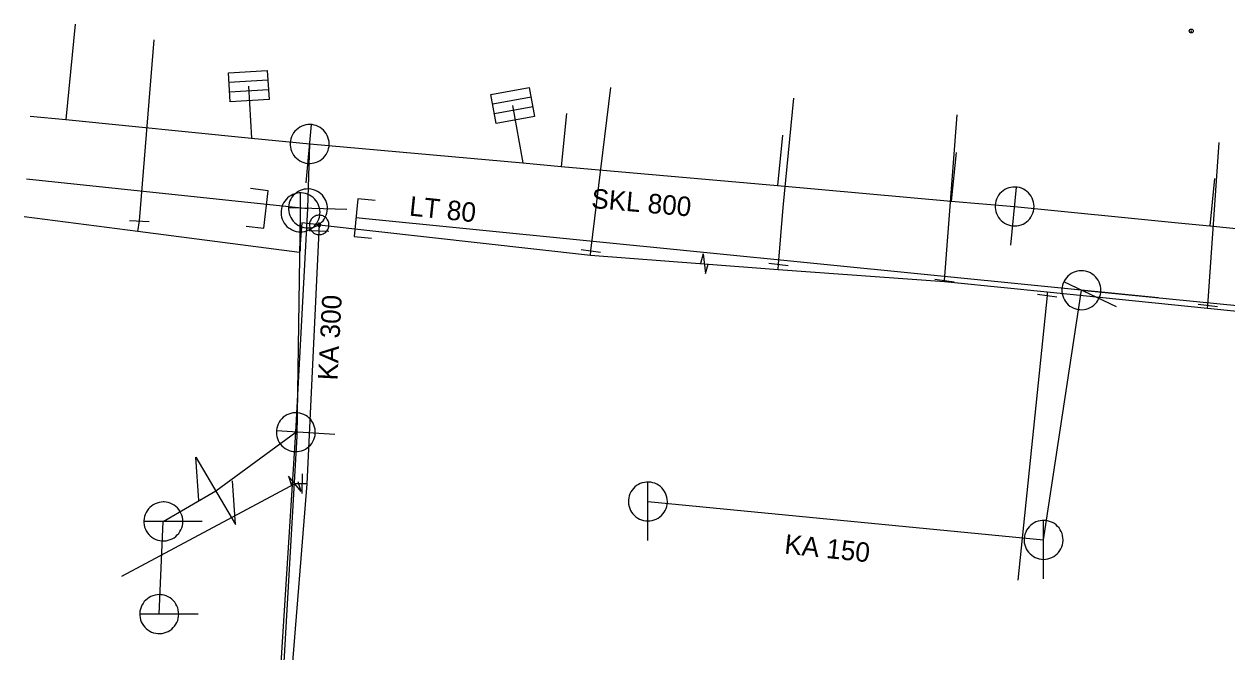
# Model space of a CAD drawing. Extents: x -783064 to -782702, y -1007904 to -1007145.
# Drawn here: x -783034.1 to -782972.3, y -1007414.2 to -1007381.9 of the extents above; entities that cross this region are included whole.
import ezdxf

# ---------------------------------------------------------------- set-up
doc = ezdxf.new("R2010")
doc.units = 0
doc.header["$LTSCALE"] = 0.4
doc.header["$PDMODE"] = 32
doc.header["$PDSIZE"] = 0.2
for name, color, linetype, lineweight in [('1', 7, 'Continuous', 13), ('11', 7, 'Continuous', 13), ('13', 7, 'Continuous', 13), ('14', 7, 'Continuous', 13), ('17', 7, 'Continuous', 25), ('22', 7, 'Continuous', 13), ('31', 7, 'Continuous', 13), ('34', 7, 'Continuous', 13), ('47', 7, 'Continuous', 13)]:
    doc.layers.add(name, color=color, linetype=linetype, lineweight=lineweight)

msp = doc.modelspace()

# ---------------------------------------------------------------- linework, layer by layer
at = {"layer": '1'}
msp.add_point((-782974.16, -1007382.289), dxfattribs=at)
at = {"layer": '11'}
for p, q in [((-783031.44, -1007381.93), (-783031.93, -1007386.84)), ((-783022.549, -1007385.119), (-783022.39, -1007387.79)), ((-783009, -1007386.109), (-783008.46, -1007389.06)), ((-783006.23, -1007386.52), (-783006.5, -1007389.24)), ((-782995.14, -1007387.63), (-782995.399, -1007390.22)), ((-782986.23, -1007388.53), (-782986.48, -1007391.02)), ((-782972.969, -1007389.86), (-782973.21, -1007392.3)), ((-783024.234, -1007405.901), (-783020.12, -1007402.89)), ((-783026.922, -1007407.474), (-783024.234, -1007405.901)), ((-783027.131, -1007412.234), (-783026.922, -1007407.474))]:
    msp.add_line(p, q, dxfattribs=at)
at = {"layer": '13'}
for p, q in [((-783028.152, -1007392.037), (-783027.383, -1007382.737)), ((-783004.98, -1007393.575), (-783003.958, -1007385.184)), ((-782986.819, -1007395.099), (-782986.17, -1007386.59)), ((-782973.317, -1007396.376), (-782972.732, -1007388.015)), ((-782981.562, -1007395.872), (-782983.061, -1007410.494)), ((-783020.171, -1007405.541), (-783029.074, -1007410.307)), ((-783019.784, -1007405.535), (-783020.171, -1007405.541))]:
    msp.add_line(p, q, dxfattribs=at)
msp.add_lwpolyline([(-782995.339, -1007394.269), (-782995.109, -1007391.35), (-782994.559, -1007385.73)], dxfattribs=at)
at = {"layer": '14', "lineweight": 25}
for p, q in [((-783019.5, -1007391.399), (-783019.409, -1007388.089)), ((-783033.95, -1007389.875), (-783019.5, -1007391.399)), ((-783020.12, -1007402.89), (-783019.5, -1007391.399)), ((-783017.033, -1007391.872), (-782975.859, -1007395.965)), ((-782981.739, -1007408.42), (-782979.802, -1007395.6)), ((-783023.759, -1007460.525), (-783020.12, -1007402.89)), ((-783002.05, -1007406.45), (-782981.739, -1007408.42))]:
    msp.add_line(p, q, dxfattribs=at)
at = {"layer": '14'}
for p, q in [((-783028.23, -1007392.582), (-783028.152, -1007392.037)), ((-783018.921, -1007392.244), (-783018.931, -1007392.572)), ((-783004.991, -1007393.792), (-783004.98, -1007393.575)), ((-782995.359, -1007394.53), (-782995.339, -1007394.269)), ((-782986.82, -1007395.16), (-782986.819, -1007395.099)), ((-782981.552, -1007395.683), (-782981.562, -1007395.872)), ((-782973.329, -1007396.518), (-782973.317, -1007396.376)), ((-783019.55, -1007405.538), (-783019.784, -1007405.535))]:
    msp.add_line(p, q, dxfattribs=at)
at = {"layer": '14', "lineweight": 25}
for points in [[(-783033.754, -1007386.657), (-783031.93, -1007386.84), (-783022.39, -1007387.79), (-783019.409, -1007388.089)], [(-783019.409, -1007388.089), (-783008.46, -1007389.06), (-783006.5, -1007389.24), (-782995.399, -1007390.22), (-782986.48, -1007391.02), (-782983.228, -1007391.299)], [(-782983.228, -1007391.299), (-782974.833, -1007392.137), (-782973.21, -1007392.3), (-782963.44, -1007393.28), (-782954.43, -1007394.18), (-782945.989, -1007395.03), (-782935.15, -1007396.194), (-782929.789, -1007396.77)], [(-783023.489, -1007462.841), (-783020.044, -1007403.091), (-783019.879, -1007391.6)], [(-782979.802, -1007395.6), (-782957.907, -1007397.75), (-782930.949, -1007400.43)]]:
    msp.add_lwpolyline(points, dxfattribs=at)
at = {"layer": '17'}
for points in [[(-783018.921, -1007392.244), (-783019.804, -1007392.144), (-783019.93, -1007393.66), (-783028.23, -1007392.582), (-783034.069, -1007391.825)], [(-783018.931, -1007392.572), (-783019.55, -1007405.538), (-783022.008, -1007435.982), (-783023.248, -1007462.969), (-783023.271, -1007463.144), (-783023.528, -1007465.299), (-783024.585, -1007485.409)], [(-783018.921, -1007392.244), (-783004.991, -1007393.792), (-782999.155, -1007394.238)], [(-782999.155, -1007394.238), (-782995.359, -1007394.53), (-782986.82, -1007395.16), (-782986.309, -1007395.2), (-782981.552, -1007395.683), (-782973.329, -1007396.518), (-782967.743, -1007397.085), (-782962.101, -1007397.658), (-782955.68, -1007398.31), (-782946.21, -1007399.37), (-782941.319, -1007399.909)]]:
    msp.add_lwpolyline(points, dxfattribs=at)
at = {"layer": '22'}
for p, q in [((-783021.554, -1007384.815), (-783023.55, -1007384.935)), ((-783021.524, -1007385.314), (-783023.52, -1007385.434)), ((-783008.049, -1007385.687), (-783010.016, -1007386.047)), ((-783007.959, -1007386.179), (-783009.926, -1007386.539)), ((-783019.585, -1007390.081), (-783019.32, -1007387.093)), ((-783019.879, -1007393.6), (-783019.878, -1007390.6)), ((-782983.426, -1007393.289), (-782983.128, -1007390.304)), ((-783017.5, -1007391.453), (-783020.499, -1007391.371)), ((-782977.992, -1007396.454), (-782980.705, -1007395.173)), ((-783018.123, -1007403.016), (-783021.117, -1007402.827)), ((-783002.05, -1007408.45), (-783002.049, -1007405.45)), ((-783024.921, -1007407.474), (-783027.921, -1007407.473)), ((-782981.739, -1007410.42), (-782981.738, -1007407.42)), ((-783025.13, -1007412.234), (-783028.13, -1007412.233))]:
    msp.add_line(p, q, dxfattribs=at)
for points in [[(-783021.494, -1007385.813), (-783023.49, -1007385.933), (-783023.58, -1007384.435), (-783021.584, -1007384.316)], [(-783007.869, -1007386.671), (-783009.836, -1007387.031), (-783010.106, -1007385.555), (-783008.139, -1007385.195)], [(-783018.412, -1007388.177), (-783018.409, -1007388.068), (-783018.417, -1007387.959), (-783018.438, -1007387.851), (-783018.469, -1007387.747), (-783018.512, -1007387.646), (-783018.566, -1007387.55), (-783018.63, -1007387.461), (-783018.703, -1007387.381), (-783018.785, -1007387.307), (-783018.874, -1007387.244), (-783018.969, -1007387.19), (-783019.071, -1007387.148), (-783019.176, -1007387.117), (-783019.283, -1007387.097), (-783019.393, -1007387.089), (-783019.502, -1007387.094), (-783019.611, -1007387.109), (-783019.717, -1007387.137), (-783019.819, -1007387.177), (-783019.915, -1007387.227), (-783020.007, -1007387.288), (-783020.091, -1007387.358), (-783020.167, -1007387.437), (-783020.234, -1007387.524), (-783020.29, -1007387.617), (-783020.336, -1007387.716), (-783020.372, -1007387.821), (-783020.395, -1007387.927), (-783020.407, -1007388.037), (-783020.406, -1007388.146), (-783020.395, -1007388.254), (-783020.37, -1007388.361), (-783020.335, -1007388.464), (-783020.289, -1007388.564), (-783020.231, -1007388.657), (-783020.164, -1007388.744), (-783020.088, -1007388.823), (-783020.004, -1007388.892), (-783019.913, -1007388.953), (-783019.815, -1007389.003), (-783019.713, -1007389.042), (-783019.607, -1007389.069), (-783019.498, -1007389.085), (-783019.389, -1007389.089), (-783019.28, -1007389.08), (-783019.173, -1007389.061), (-783019.067, -1007389.029), (-783018.966, -1007388.986), (-783018.871, -1007388.932), (-783018.782, -1007388.868), (-783018.7, -1007388.795), (-783018.628, -1007388.714), (-783018.564, -1007388.625), (-783018.511, -1007388.529), (-783018.468, -1007388.429), (-783018.436, -1007388.323), (-783018.417, -1007388.215)], [(-783018.879, -1007391.6), (-783018.884, -1007391.491), (-783018.902, -1007391.383), (-783018.932, -1007391.277), (-783018.972, -1007391.176), (-783019.024, -1007391.079), (-783019.086, -1007390.989), (-783019.158, -1007390.906), (-783019.238, -1007390.832), (-783019.326, -1007390.766), (-783019.42, -1007390.711), (-783019.52, -1007390.666), (-783019.625, -1007390.633), (-783019.732, -1007390.611), (-783019.841, -1007390.601), (-783019.951, -1007390.603), (-783020.059, -1007390.617), (-783020.166, -1007390.642), (-783020.269, -1007390.679), (-783020.367, -1007390.728), (-783020.459, -1007390.786), (-783020.545, -1007390.855), (-783020.622, -1007390.932), (-783020.691, -1007391.018), (-783020.75, -1007391.11), (-783020.798, -1007391.208), (-783020.835, -1007391.311), (-783020.861, -1007391.418), (-783020.875, -1007391.526), (-783020.878, -1007391.636), (-783020.868, -1007391.745), (-783020.847, -1007391.852), (-783020.813, -1007391.956), (-783020.769, -1007392.056), (-783020.714, -1007392.151), (-783020.648, -1007392.239), (-783020.574, -1007392.319), (-783020.491, -1007392.391), (-783020.401, -1007392.453), (-783020.305, -1007392.505), (-783020.203, -1007392.546), (-783020.098, -1007392.576), (-783019.99, -1007392.594), (-783019.88, -1007392.6), (-783019.771, -1007392.594), (-783019.663, -1007392.576), (-783019.558, -1007392.547), (-783019.456, -1007392.506), (-783019.359, -1007392.454), (-783019.269, -1007392.392), (-783019.186, -1007392.321), (-783019.111, -1007392.241), (-783019.046, -1007392.153), (-783018.99, -1007392.059), (-783018.946, -1007391.959), (-783018.912, -1007391.855), (-783018.89, -1007391.747), (-783018.88, -1007391.638)], [(-783019.472, -1007390.399), (-783019.581, -1007390.402), (-783019.689, -1007390.417), (-783019.796, -1007390.444), (-783019.898, -1007390.481), (-783019.997, -1007390.531), (-783020.088, -1007390.59), (-783020.173, -1007390.66), (-783020.249, -1007390.738), (-783020.318, -1007390.824), (-783020.375, -1007390.916), (-783020.423, -1007391.015), (-783020.459, -1007391.119), (-783020.484, -1007391.226), (-783020.497, -1007391.334), (-783020.498, -1007391.444), (-783020.487, -1007391.553), (-783020.464, -1007391.66), (-783020.43, -1007391.764), (-783020.384, -1007391.864), (-783020.329, -1007391.957), (-783020.262, -1007392.045), (-783020.187, -1007392.124), (-783020.103, -1007392.195), (-783020.013, -1007392.257), (-783019.916, -1007392.308), (-783019.814, -1007392.347), (-783019.708, -1007392.376), (-783019.6, -1007392.393), (-783019.49, -1007392.398), (-783019.381, -1007392.391), (-783019.273, -1007392.373), (-783019.169, -1007392.342), (-783019.067, -1007392.301), (-783018.971, -1007392.248), (-783018.881, -1007392.185), (-783018.799, -1007392.113), (-783018.725, -1007392.032), (-783018.661, -1007391.944), (-783018.606, -1007391.849), (-783018.562, -1007391.748), (-783018.529, -1007391.644), (-783018.508, -1007391.537), (-783018.499, -1007391.427), (-783018.502, -1007391.318), (-783018.517, -1007391.209), (-783018.544, -1007391.103), (-783018.582, -1007391), (-783018.631, -1007390.902), (-783018.691, -1007390.81), (-783018.759, -1007390.725), (-783018.837, -1007390.648), (-783018.924, -1007390.581), (-783019.016, -1007390.522), (-783019.115, -1007390.476), (-783019.218, -1007390.439), (-783019.325, -1007390.414), (-783019.434, -1007390.401)], [(-782982.232, -1007391.398), (-782982.228, -1007391.289), (-782982.235, -1007391.18), (-782982.254, -1007391.072), (-782982.284, -1007390.967), (-782982.326, -1007390.865), (-782982.379, -1007390.77), (-782982.442, -1007390.68), (-782982.514, -1007390.598), (-782982.595, -1007390.524), (-782982.684, -1007390.46), (-782982.779, -1007390.405), (-782982.88, -1007390.362), (-782982.984, -1007390.329), (-782983.092, -1007390.309), (-782983.201, -1007390.3), (-782983.31, -1007390.303), (-782983.419, -1007390.317), (-782983.525, -1007390.344), (-782983.628, -1007390.383), (-782983.725, -1007390.431), (-782983.817, -1007390.491), (-782983.902, -1007390.56), (-782983.979, -1007390.639), (-782984.047, -1007390.725), (-782984.104, -1007390.818), (-782984.151, -1007390.916), (-782984.188, -1007391.02), (-782984.212, -1007391.126), (-782984.225, -1007391.236), (-782984.226, -1007391.345), (-782984.216, -1007391.454), (-782984.192, -1007391.56), (-782984.158, -1007391.664), (-782984.113, -1007391.764), (-782984.056, -1007391.858), (-782983.991, -1007391.945), (-782983.915, -1007392.025), (-782983.832, -1007392.096), (-782983.741, -1007392.157), (-782983.644, -1007392.208), (-782983.542, -1007392.248), (-782983.437, -1007392.277), (-782983.328, -1007392.294), (-782983.219, -1007392.299), (-782983.11, -1007392.292), (-782983.002, -1007392.273), (-782982.897, -1007392.243), (-782982.795, -1007392.2), (-782982.699, -1007392.148), (-782982.61, -1007392.085), (-782982.527, -1007392.013), (-782982.454, -1007391.932), (-782982.389, -1007391.844), (-782982.335, -1007391.749), (-782982.291, -1007391.649), (-782982.258, -1007391.543), (-782982.237, -1007391.436)], [(-782979.374, -1007394.695), (-782979.475, -1007394.654), (-782979.581, -1007394.624), (-782979.689, -1007394.606), (-782979.798, -1007394.599), (-782979.908, -1007394.605), (-782980.015, -1007394.623), (-782980.121, -1007394.652), (-782980.222, -1007394.693), (-782980.32, -1007394.744), (-782980.409, -1007394.806), (-782980.493, -1007394.877), (-782980.567, -1007394.958), (-782980.633, -1007395.045), (-782980.689, -1007395.14), (-782980.734, -1007395.24), (-782980.767, -1007395.344), (-782980.79, -1007395.451), (-782980.801, -1007395.56), (-782980.798, -1007395.67), (-782980.785, -1007395.778), (-782980.76, -1007395.885), (-782980.723, -1007395.987), (-782980.674, -1007396.086), (-782980.616, -1007396.179), (-782980.548, -1007396.264), (-782980.471, -1007396.342), (-782980.385, -1007396.411), (-782980.294, -1007396.47), (-782980.195, -1007396.518), (-782980.092, -1007396.556), (-782979.986, -1007396.583), (-782979.878, -1007396.596), (-782979.769, -1007396.599), (-782979.659, -1007396.59), (-782979.552, -1007396.568), (-782979.448, -1007396.535), (-782979.347, -1007396.491), (-782979.253, -1007396.436), (-782979.165, -1007396.371), (-782979.084, -1007396.297), (-782979.012, -1007396.214), (-782978.95, -1007396.124), (-782978.897, -1007396.028), (-782978.856, -1007395.926), (-782978.826, -1007395.821), (-782978.808, -1007395.714), (-782978.801, -1007395.604), (-782978.807, -1007395.494), (-782978.824, -1007395.386), (-782978.853, -1007395.281), (-782978.894, -1007395.179), (-782978.945, -1007395.083), (-782979.006, -1007394.992), (-782979.078, -1007394.909), (-782979.158, -1007394.834), (-782979.246, -1007394.768), (-782979.34, -1007394.713)], [(-783020.056, -1007401.892), (-783020.165, -1007401.891), (-783020.274, -1007401.902), (-783020.382, -1007401.925), (-783020.485, -1007401.959), (-783020.585, -1007402.004), (-783020.679, -1007402.061), (-783020.766, -1007402.127), (-783020.845, -1007402.202), (-783020.917, -1007402.286), (-783020.977, -1007402.376), (-783021.029, -1007402.473), (-783021.068, -1007402.576), (-783021.097, -1007402.681), (-783021.114, -1007402.79), (-783021.119, -1007402.9), (-783021.111, -1007403.008), (-783021.093, -1007403.117), (-783021.063, -1007403.222), (-783021.02, -1007403.323), (-783020.968, -1007403.418), (-783020.905, -1007403.508), (-783020.833, -1007403.59), (-783020.751, -1007403.664), (-783020.663, -1007403.729), (-783020.568, -1007403.783), (-783020.468, -1007403.826), (-783020.363, -1007403.859), (-783020.256, -1007403.88), (-783020.146, -1007403.889), (-783020.037, -1007403.886), (-783019.929, -1007403.871), (-783019.823, -1007403.844), (-783019.72, -1007403.806), (-783019.622, -1007403.758), (-783019.53, -1007403.697), (-783019.445, -1007403.628), (-783019.368, -1007403.55), (-783019.301, -1007403.464), (-783019.243, -1007403.372), (-783019.195, -1007403.273), (-783019.159, -1007403.17), (-783019.134, -1007403.063), (-783019.121, -1007402.954), (-783019.12, -1007402.844), (-783019.131, -1007402.735), (-783019.154, -1007402.629), (-783019.188, -1007402.524), (-783019.234, -1007402.424), (-783019.29, -1007402.331), (-783019.356, -1007402.243), (-783019.431, -1007402.163), (-783019.515, -1007402.093), (-783019.605, -1007402.031), (-783019.702, -1007401.981), (-783019.804, -1007401.941), (-783019.91, -1007401.912), (-783020.018, -1007401.895)], [(-783001.05, -1007406.45), (-783001.055, -1007406.341), (-783001.073, -1007406.233), (-783001.103, -1007406.127), (-783001.143, -1007406.026), (-783001.195, -1007405.929), (-783001.257, -1007405.839), (-783001.329, -1007405.756), (-783001.409, -1007405.682), (-783001.497, -1007405.616), (-783001.591, -1007405.561), (-783001.691, -1007405.516), (-783001.796, -1007405.483), (-783001.903, -1007405.461), (-783002.012, -1007405.451), (-783002.122, -1007405.453), (-783002.23, -1007405.467), (-783002.337, -1007405.492), (-783002.44, -1007405.529), (-783002.538, -1007405.578), (-783002.63, -1007405.636), (-783002.716, -1007405.705), (-783002.793, -1007405.782), (-783002.862, -1007405.868), (-783002.921, -1007405.96), (-783002.969, -1007406.058), (-783003.006, -1007406.161), (-783003.032, -1007406.268), (-783003.046, -1007406.376), (-783003.049, -1007406.486), (-783003.039, -1007406.595), (-783003.018, -1007406.702), (-783002.984, -1007406.806), (-783002.94, -1007406.906), (-783002.885, -1007407.001), (-783002.819, -1007407.089), (-783002.745, -1007407.169), (-783002.662, -1007407.241), (-783002.572, -1007407.303), (-783002.476, -1007407.355), (-783002.374, -1007407.396), (-783002.269, -1007407.426), (-783002.161, -1007407.444), (-783002.051, -1007407.45), (-783001.942, -1007407.444), (-783001.834, -1007407.426), (-783001.729, -1007407.397), (-783001.627, -1007407.356), (-783001.53, -1007407.304), (-783001.44, -1007407.242), (-783001.357, -1007407.171), (-783001.282, -1007407.091), (-783001.217, -1007407.003), (-783001.161, -1007406.909), (-783001.117, -1007406.809), (-783001.083, -1007406.705), (-783001.061, -1007406.597), (-783001.051, -1007406.488)], [(-783026.921, -1007406.474), (-783027.03, -1007406.479), (-783027.138, -1007406.497), (-783027.244, -1007406.527), (-783027.345, -1007406.567), (-783027.442, -1007406.619), (-783027.532, -1007406.681), (-783027.615, -1007406.753), (-783027.689, -1007406.833), (-783027.755, -1007406.921), (-783027.81, -1007407.015), (-783027.855, -1007407.115), (-783027.888, -1007407.22), (-783027.91, -1007407.327), (-783027.92, -1007407.436), (-783027.918, -1007407.546), (-783027.904, -1007407.654), (-783027.879, -1007407.761), (-783027.842, -1007407.864), (-783027.793, -1007407.962), (-783027.735, -1007408.054), (-783027.666, -1007408.14), (-783027.589, -1007408.217), (-783027.503, -1007408.286), (-783027.411, -1007408.345), (-783027.313, -1007408.393), (-783027.21, -1007408.43), (-783027.103, -1007408.456), (-783026.995, -1007408.47), (-783026.885, -1007408.473), (-783026.776, -1007408.463), (-783026.669, -1007408.442), (-783026.565, -1007408.408), (-783026.465, -1007408.364), (-783026.37, -1007408.309), (-783026.282, -1007408.243), (-783026.202, -1007408.169), (-783026.13, -1007408.086), (-783026.068, -1007407.996), (-783026.016, -1007407.9), (-783025.975, -1007407.798), (-783025.945, -1007407.693), (-783025.927, -1007407.585), (-783025.921, -1007407.475), (-783025.927, -1007407.366), (-783025.945, -1007407.258), (-783025.974, -1007407.153), (-783026.015, -1007407.051), (-783026.067, -1007406.954), (-783026.129, -1007406.864), (-783026.2, -1007406.781), (-783026.28, -1007406.706), (-783026.368, -1007406.641), (-783026.462, -1007406.585), (-783026.562, -1007406.541), (-783026.666, -1007406.507), (-783026.774, -1007406.485), (-783026.883, -1007406.475)], [(-782980.739, -1007408.42), (-782980.744, -1007408.311), (-782980.762, -1007408.203), (-782980.792, -1007408.097), (-782980.832, -1007407.996), (-782980.884, -1007407.899), (-782980.946, -1007407.809), (-782981.018, -1007407.726), (-782981.098, -1007407.652), (-782981.186, -1007407.586), (-782981.28, -1007407.531), (-782981.38, -1007407.486), (-782981.485, -1007407.453), (-782981.592, -1007407.431), (-782981.701, -1007407.421), (-782981.811, -1007407.423), (-782981.919, -1007407.437), (-782982.026, -1007407.462), (-782982.129, -1007407.499), (-782982.227, -1007407.548), (-782982.319, -1007407.606), (-782982.405, -1007407.675), (-782982.482, -1007407.752), (-782982.551, -1007407.838), (-782982.61, -1007407.93), (-782982.658, -1007408.028), (-782982.695, -1007408.131), (-782982.721, -1007408.238), (-782982.735, -1007408.346), (-782982.738, -1007408.456), (-782982.728, -1007408.565), (-782982.707, -1007408.672), (-782982.673, -1007408.776), (-782982.629, -1007408.876), (-782982.574, -1007408.971), (-782982.508, -1007409.059), (-782982.434, -1007409.139), (-782982.351, -1007409.211), (-782982.261, -1007409.273), (-782982.165, -1007409.325), (-782982.063, -1007409.366), (-782981.958, -1007409.396), (-782981.85, -1007409.414), (-782981.74, -1007409.42), (-782981.631, -1007409.414), (-782981.523, -1007409.396), (-782981.418, -1007409.367), (-782981.316, -1007409.326), (-782981.219, -1007409.274), (-782981.129, -1007409.212), (-782981.046, -1007409.141), (-782980.971, -1007409.061), (-782980.906, -1007408.973), (-782980.85, -1007408.879), (-782980.806, -1007408.779), (-782980.772, -1007408.675), (-782980.75, -1007408.567), (-782980.74, -1007408.458)], [(-783027.13, -1007411.234), (-783027.239, -1007411.239), (-783027.347, -1007411.257), (-783027.453, -1007411.287), (-783027.554, -1007411.327), (-783027.651, -1007411.379), (-783027.741, -1007411.441), (-783027.824, -1007411.513), (-783027.898, -1007411.593), (-783027.964, -1007411.681), (-783028.019, -1007411.775), (-783028.064, -1007411.875), (-783028.097, -1007411.98), (-783028.119, -1007412.087), (-783028.129, -1007412.196), (-783028.127, -1007412.306), (-783028.113, -1007412.414), (-783028.088, -1007412.521), (-783028.051, -1007412.624), (-783028.002, -1007412.722), (-783027.944, -1007412.814), (-783027.875, -1007412.9), (-783027.798, -1007412.977), (-783027.712, -1007413.046), (-783027.62, -1007413.105), (-783027.522, -1007413.153), (-783027.419, -1007413.19), (-783027.312, -1007413.216), (-783027.204, -1007413.23), (-783027.094, -1007413.233), (-783026.985, -1007413.223), (-783026.878, -1007413.202), (-783026.774, -1007413.168), (-783026.674, -1007413.124), (-783026.579, -1007413.069), (-783026.491, -1007413.003), (-783026.411, -1007412.929), (-783026.339, -1007412.846), (-783026.277, -1007412.756), (-783026.225, -1007412.66), (-783026.184, -1007412.558), (-783026.154, -1007412.453), (-783026.136, -1007412.345), (-783026.13, -1007412.235), (-783026.136, -1007412.126), (-783026.154, -1007412.018), (-783026.183, -1007411.913), (-783026.224, -1007411.811), (-783026.276, -1007411.714), (-783026.338, -1007411.624), (-783026.409, -1007411.541), (-783026.489, -1007411.466), (-783026.577, -1007411.401), (-783026.671, -1007411.345), (-783026.771, -1007411.301), (-783026.875, -1007411.267), (-783026.983, -1007411.245), (-783027.092, -1007411.235)]]:
    msp.add_lwpolyline(points, close=True, dxfattribs=at)
at = {"layer": '31'}
for points in [[(-783022.665, -1007392.303), (-783021.77, -1007392.407), (-783021.546, -1007390.488), (-783022.441, -1007390.384)], [(-783016.044, -1007390.996), (-783016.941, -1007390.91), (-783017.125, -1007392.833), (-783016.228, -1007392.919)], [(-783025.096, -1007406.406), (-783025.244, -1007404.175), (-783023.223, -1007407.627), (-783023.37, -1007405.396)]]:
    msp.add_lwpolyline(points, dxfattribs=at)
at = {"layer": '34'}
for p, q in [((-783028.653, -1007392.013), (-783027.654, -1007392.065)), ((-783018.431, -1007392.586), (-783019.43, -1007392.556)), ((-783005.476, -1007393.512), (-783004.484, -1007393.638)), ((-782995.835, -1007394.206), (-782994.843, -1007394.332)), ((-782987.315, -1007395.036), (-782986.323, -1007395.162)), ((-782982.058, -1007395.809), (-782981.066, -1007395.935)), ((-782973.813, -1007396.313), (-782972.821, -1007396.439)), ((-783019.789, -1007406.034), (-783019.777, -1007405.035))]:
    msp.add_line(p, q, dxfattribs=at)
at = {"layer": '47'}
for p, q in [((-782999.214, -1007393.731), (-782999.355, -1007394.222)), ((-783019.848, -1007405.935), (-783019.993, -1007405.446))]:
    msp.add_line(p, q, dxfattribs=at)
for points in [[(-783018.423, -1007392.291), (-783018.421, -1007392.239), (-783018.424, -1007392.186), (-783018.433, -1007392.135), (-783018.446, -1007392.085), (-783018.466, -1007392.036), (-783018.49, -1007391.989), (-783018.52, -1007391.946), (-783018.553, -1007391.906), (-783018.59, -1007391.869), (-783018.631, -1007391.836), (-783018.675, -1007391.808), (-783018.722, -1007391.785), (-783018.771, -1007391.767), (-783018.822, -1007391.754), (-783018.873, -1007391.746), (-783018.925, -1007391.744), (-783018.978, -1007391.747), (-783019.03, -1007391.756), (-783019.079, -1007391.769), (-783019.128, -1007391.789), (-783019.175, -1007391.813), (-783019.219, -1007391.842), (-783019.259, -1007391.876), (-783019.296, -1007391.913), (-783019.328, -1007391.954), (-783019.356, -1007391.998), (-783019.38, -1007392.045), (-783019.397, -1007392.094), (-783019.41, -1007392.145), (-783019.418, -1007392.196), (-783019.42, -1007392.248), (-783019.417, -1007392.301), (-783019.409, -1007392.353), (-783019.395, -1007392.402), (-783019.375, -1007392.451), (-783019.351, -1007392.498), (-783019.323, -1007392.542), (-783019.289, -1007392.582), (-783019.251, -1007392.619), (-783019.21, -1007392.651), (-783019.166, -1007392.679), (-783019.12, -1007392.703), (-783019.07, -1007392.72), (-783019.019, -1007392.733), (-783018.968, -1007392.741), (-783018.916, -1007392.743), (-783018.863, -1007392.74), (-783018.812, -1007392.732), (-783018.762, -1007392.718), (-783018.713, -1007392.698), (-783018.666, -1007392.674), (-783018.623, -1007392.645), (-783018.583, -1007392.612), (-783018.546, -1007392.574), (-783018.513, -1007392.533), (-783018.485, -1007392.489), (-783018.462, -1007392.443), (-783018.444, -1007392.393), (-783018.431, -1007392.342)], [(-783018.839, -1007392.251), (-783018.838, -1007392.242), (-783018.839, -1007392.234), (-783018.84, -1007392.226), (-783018.843, -1007392.218), (-783018.846, -1007392.209), (-783018.85, -1007392.202), (-783018.855, -1007392.195), (-783018.86, -1007392.188), (-783018.866, -1007392.182), (-783018.873, -1007392.177), (-783018.881, -1007392.172), (-783018.888, -1007392.168), (-783018.896, -1007392.165), (-783018.904, -1007392.163), (-783018.913, -1007392.162), (-783018.922, -1007392.161), (-783018.93, -1007392.162), (-783018.938, -1007392.163), (-783018.946, -1007392.166), (-783018.955, -1007392.169), (-783018.962, -1007392.173), (-783018.969, -1007392.178), (-783018.976, -1007392.183), (-783018.983, -1007392.189), (-783018.987, -1007392.196), (-783018.992, -1007392.204), (-783018.996, -1007392.211), (-783018.999, -1007392.219), (-783019.001, -1007392.227), (-783019.002, -1007392.236), (-783019.003, -1007392.245), (-783019.002, -1007392.253), (-783019.001, -1007392.261), (-783018.998, -1007392.269), (-783018.995, -1007392.278), (-783018.992, -1007392.285), (-783018.986, -1007392.292), (-783018.981, -1007392.299), (-783018.975, -1007392.306), (-783018.968, -1007392.31), (-783018.96, -1007392.315), (-783018.953, -1007392.319), (-783018.945, -1007392.322), (-783018.937, -1007392.324), (-783018.928, -1007392.325), (-783018.919, -1007392.326), (-783018.911, -1007392.325), (-783018.903, -1007392.324), (-783018.895, -1007392.321), (-783018.886, -1007392.318), (-783018.879, -1007392.315), (-783018.872, -1007392.309), (-783018.865, -1007392.304), (-783018.859, -1007392.298), (-783018.854, -1007392.291), (-783018.849, -1007392.283), (-783018.845, -1007392.276), (-783018.842, -1007392.268), (-783018.84, -1007392.26)]]:
    msp.add_lwpolyline(points, close=True, dxfattribs=at)
for points in [[(-782999.214, -1007393.731), (-782999.095, -1007394.744), (-782998.954, -1007394.253)], [(-783019.848, -1007405.935), (-783020.493, -1007405.146), (-783020.348, -1007405.635)]]:
    msp.add_lwpolyline(points, dxfattribs=at)

# ---------------------------------------------------------------- texts
at = {"layer": '1'}
for s, rotation, p in [('LT 80 ', 354, (-783014.33, -1007391.761)), ('SKL 800 ', 355, (-783004.981, -1007391.37)), ('KA 300', 87, (-783017.988, -1007400.246)), ('KA 150', 354, (-782995.072, -1007409.121))]:
    msp.add_text(s, height=1, rotation=rotation, dxfattribs=at).set_placement(p)

doc.saveas('drawing.dxf')
